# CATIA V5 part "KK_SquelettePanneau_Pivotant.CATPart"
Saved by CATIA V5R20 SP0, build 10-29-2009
Part number: Squelette_panneau_pivotant
Bounding box of the stored display mesh (mm): x -256 to 200, y -200 to 1056, z -1280 to 0
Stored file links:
  G:\Khaled_CFAO_2011\ST2M\ST2M_GR2\aboulegue\Khaled\CAD_thinkMOTION\KK_SquelettePanneau_Pivotant.CATPart
  G:\Khaled_CFAO_2011\ST2M\ST2M_GR2\aboulegue\Khaled\CAD_thinkMOTION\KK_Train_Atterrissage.CATProduct
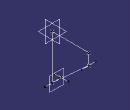
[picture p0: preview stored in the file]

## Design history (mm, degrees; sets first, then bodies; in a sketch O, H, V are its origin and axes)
Set1
  Plane1 "Plan reference": linked copy from another document
  Point1 to Point4: linked copy from another document
  Point5 "Point.10": linked copy from another document
  Plane2 "Plan reference 2": linked copy from another document
Set2 "set_squelette_panneau_pivotant"
  Line1: type Normal, RefPoint Point2, RefSkin Plane1, Start -200, End 200
  Line2: type PtPt, FirstPoint Point1, SecondPoint Point2
  Line3: type PtPt, FirstPoint Point1, SecondPoint Point3
  Line4: type PtPt, FirstPoint Point3, SecondPoint Point4
  Line5: type PtPt, FirstPoint Point4, SecondPoint Point2
  Line6: type Normal, RefPoint Point4, RefSkin Plane1, Start -200, End 200
  Line7: type PtPt, FirstPoint Point4, SecondPoint Point5
  Line8: type Normal, RefPoint Point5, RefSkin Plane2, Start -200, End 200
  Plane3 "Plan panneau pivotant1": type 2Lines, Element1 Line7, Element2 Line4
Body1 (main body)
